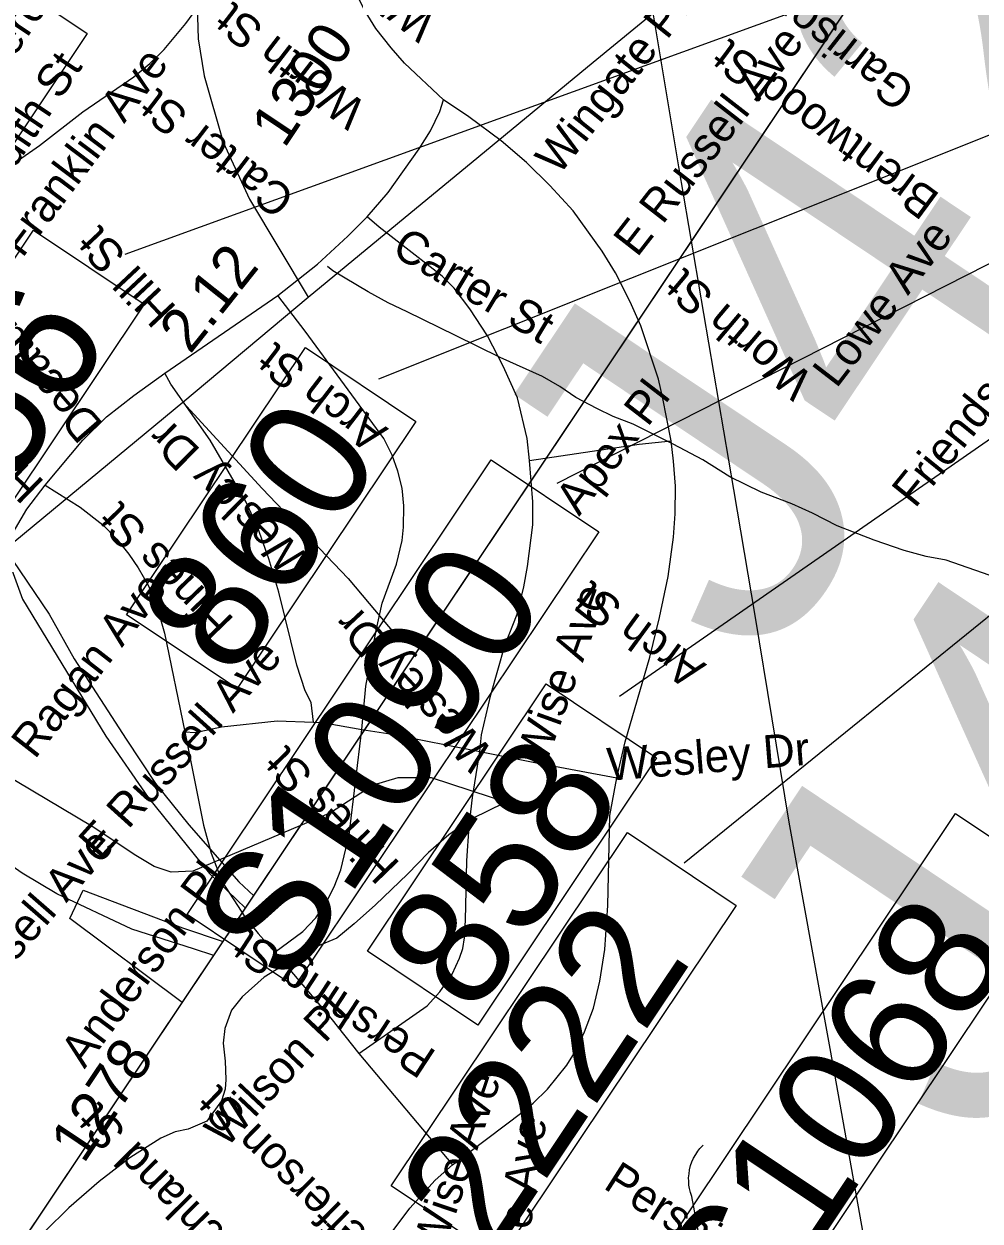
# Model space of a CAD drawing. Extents: x 1716282 to 1717158, y 799307 to 801078.
# Drawn here: x 1716855.7 to 1716895.7, y 800733.7 to 800783.8 of the extents above; entities that cross this region are included whole.
import ezdxf

# ---------------------------------------------------------------- set-up
doc = ezdxf.new("R2010")
doc.units = 0
for name, color, linetype in [('Exist Boundary Political City Limit New', 7, 'Continuous'), ('Exist Hydrographic Misc Water Feature', 7, 'Continuous'), ('Exist Road Non-System Structure Non-Sys Other Number Label', 7, 'Continuous'), ('Exist Road Non-System Type 51', 7, 'Continuous'), ('Exist Road Non-System Type 51 Label', 7, 'Continuous'), ('Exist Road Primary Interstate Structure Ovrhead Sign CELL', 7, 'Continuous'), ('Exist Road Primary NC Attributed', 7, 'Continuous'), ('Exist Road Primary US Structure Ovrhead Sign CELL', 7, 'Continuous'), ('Exist Road Primary US Structure Pipe Number Label', 7, 'Continuous'), ('Exist Road Primary US Structure Standard Bridge Number Label', 7, 'Continuous'), ('Exist Road Secondary Mileage Tenths English Label', 7, 'Continuous'), ('Exist Road Secondary Type 51 Attributed', 7, 'Continuous'), ('Exist Road Secondary Type 51 Number Label', 7, 'Continuous'), ('Exist Utilities Electrical Transmission Line', 7, 'Continuous'), ('Map Preparation Boundary City Limit Buffer Line', 7, 'Continuous'), ('Prop DSN Text', 7, 'Continuous')]:
    doc.layers.add(name, color=color, linetype=linetype)

msp = doc.modelspace()

# ---------------------------------------------------------------- linework, layer by layer
at = {"layer": 'Exist Boundary Political City Limit New'}
for points in [[(1716834.11, 800763.795), (1716833.305, 800760.022), (1716832.112, 800757.372), (1716829.513, 800751.6), (1716828.118, 800748.504), (1716830.111, 800743.692), (1716849.41, 800759.889), (1716847.021, 800765.269), (1716846.178, 800767.852), (1716845.613, 800770.743), (1716845.226, 800773.688), (1716850.853, 800766.071), (1716851.697, 800766.703), (1716854.143, 800763.725), (1716855.625, 800759.697), (1716859.113, 800753.96), (1716860.899, 800751.388), (1716863.463, 800748.209), (1716864.965, 800746.757)], [(1716862.323, 800742.81), (1716857.612, 800746.321), (1716858.169, 800747.509), (1716862.329, 800745.932), (1716864.031, 800745.362)]]:
    msp.add_lwpolyline(points, dxfattribs=at)
at = {"layer": 'Exist Hydrographic Misc Water Feature'}
for points in [[(1716896.454, 800760.586), (1716894.33, 800761.333), (1716893.487, 800761.488), (1716892.565, 800761.731), (1716891.314, 800762.164), (1716889.76, 800762.769), (1716888.721, 800763.304), (1716887.855, 800763.685), (1716886.574, 800764.173), (1716885.261, 800764.824), (1716884.126, 800765.528), (1716882.895, 800766.193), (1716881.216, 800767.025), (1716880.381, 800767.347), (1716879.693, 800767.677), (1716878.814, 800768.139), (1716878.143, 800768.597), (1716877.415, 800769.023), (1716875.638, 800769.815), (1716873.775, 800770.739), (1716871.751, 800771.736), (1716870.949, 800772.106), (1716870.11, 800772.573), (1716868.631, 800773.443), (1716868.408, 800773.63)], [(1716876.042, 800751.14), (1716872.76, 800752.217), (1716871.349, 800752.22), (1716870.316, 800751.909), (1716868.528, 800750.75), (1716862.768, 800748.302), (1716861.859, 800748.263), (1716861.14, 800748.508), (1716860.381, 800748.958), (1716858.551, 800750.182), (1716851.597, 800754.307), (1716846.485, 800758.817), (1716843.528, 800759.819), (1716840.189, 800759.612), (1716836.246, 800760.699), (1716833.061, 800762.288), (1716827.152, 800765.878), (1716824.331, 800768.986), (1716822.573, 800770.041), (1716821.851, 800770.088)], [(1716875.987, 800751.251), (1716874.936, 800750.732), (1716874.44, 800750.504), (1716873.496, 800749.833), (1716872.636, 800749.086), (1716871.761, 800748.174), (1716870.421, 800746.891), (1716869.527, 800746.096), (1716868.798, 800745.505), (1716867.619, 800745.013), (1716865.746, 800743.866), (1716864.837, 800743.049), (1716864.379, 800742.482), (1716864.106, 800741.721), (1716864.034, 800741.101), (1716864.115, 800740.346), (1716864.153, 800739.58), (1716864.125, 800739.178), (1716863.967, 800738.688), (1716863.353, 800737.843), (1716862.562, 800737.507), (1716862.021, 800737.384), (1716861.423, 800737.125), (1716860.118, 800736.295), (1716858.844, 800735.303), (1716857.569, 800734.207), (1716856.583, 800733.23)]]:
    msp.add_lwpolyline(points, dxfattribs=at)
at = {"layer": 'Exist Road Non-System Type 51'}
for p, q in [((1716861.586, 800769.158), (1716866.326, 800772.415)), ((1716869.721, 800740.677), (1716873.65, 800736.011))]:
    msp.add_line(p, q, dxfattribs=at)
for points in [[(1716873.268, 800780.604), (1716871.626, 800782.148), (1716871.068, 800782.779), (1716870.435, 800783.591), (1716869.985, 800784.322), (1716869.676, 800784.941), (1716869.32, 800785.79), (1716869.061, 800786.567), (1716868.648, 800788.468), (1716868.622, 800789.284)], [(1716842.177, 800775.411), (1716842.533, 800775.21), (1716842.752, 800775.21), (1716843.723, 800775.6), (1716844.159, 800775.703), (1716844.543, 800775.743), (1716848.824, 800775.818), (1716850.05, 800775.959), (1716851.719, 800776.353), (1716853.383, 800776.943), (1716854.509, 800777.498), (1716855.466, 800778.077), (1716856.334, 800778.695), (1716858.161, 800780.1), (1716860.29, 800781.57), (1716860.959, 800782.125), (1716861.565, 800782.714), (1716862.464, 800783.805), (1716863.245, 800784.863)], [(1716870.072, 800775.714), (1716870.95, 800776.725), (1716872.253, 800778.555), (1716872.716, 800779.303), (1716873.119, 800780.115), (1716873.268, 800780.604)], [(1716882.799, 800766.321), (1716882.446, 800768.175), (1716882.272, 800768.914), (1716881.539, 800771.149), (1716881.094, 800772.147), (1716880.467, 800773.36), (1716879.918, 800774.271), (1716878.706, 800775.956), (1716877.727, 800777.024), (1716876.75, 800777.986), (1716875.68, 800778.885), (1716874.323, 800779.889), (1716873.268, 800780.604)], [(1716866.326, 800772.415), (1716867.991, 800773.732), (1716869.254, 800774.902), (1716870.072, 800775.714)], [(1716876.867, 800765.497), (1716876.773, 800766.419), (1716876.374, 800768.126), (1716875.772, 800769.458), (1716875.105, 800770.725), (1716874.372, 800771.861), (1716873.711, 800772.715), (1716873.209, 800773.23), (1716870.569, 800775.281), (1716870.072, 800775.714)], [(1716869.842, 800754.234), (1716870.013, 800756.052), (1716870.443, 800758.384), (1716870.698, 800759.528), (1716871.299, 800761.159), (1716871.531, 800762.157), (1716871.591, 800762.712), (1716871.598, 800763.611), (1716871.535, 800764.344), (1716871.358, 800765.054), (1716871.118, 800765.727), (1716870.764, 800766.43), (1716867.471, 800770.925), (1716866.326, 800772.415)], [(1716856.579, 800764.477), (1716858.153, 800766.35), (1716859.145, 800767.331), (1716860.288, 800768.232), (1716861.586, 800769.158)], [(1716867.823, 800754.552), (1716867.728, 800755.365), (1716867.464, 800755.854), (1716867.125, 800756.927), (1716866.371, 800759.984), (1716865.949, 800761.391), (1716865.482, 800762.684), (1716864.993, 800763.759), (1716863.49, 800766.359), (1716861.84, 800768.698), (1716861.586, 800769.158)], [(1716876.867, 800765.497), (1716881.471, 800766.184), (1716882.799, 800766.321)], [(1716880.523, 800752.219), (1716880.881, 800753.725), (1716881.905, 800757.266), (1716882.314, 800758.925), (1716882.678, 800760.646), (1716882.904, 800762.29), (1716882.973, 800763.269), (1716882.981, 800764.428), (1716882.906, 800765.482), (1716882.799, 800766.321)], [(1716874.782, 800753.323), (1716874.852, 800754.022), (1716875.246, 800755.686), (1716875.834, 800757.761), (1716876.347, 800759.062), (1716876.629, 800760.215), (1716876.786, 800761.058), (1716877.009, 800762.815), (1716877.006, 800763.769), (1716876.867, 800765.497)], [(1716852.694, 800753.43), (1716853.477, 800757.962), (1716854.094, 800759.998), (1716854.689, 800761.46), (1716855.096, 800762.246), (1716855.813, 800763.469), (1716856.579, 800764.477)], [(1716856.579, 800764.477), (1716858.043, 800763.551), (1716858.998, 800762.803), (1716859.58, 800762.206), (1716860.086, 800761.588), (1716860.48, 800761.015), (1716860.886, 800760.279), (1716861.227, 800759.488), (1716861.577, 800758.274), (1716862.428, 800754.145)], [(1716862.428, 800754.145), (1716862.859, 800754.119), (1716863.966, 800754.357), (1716866.292, 800754.604), (1716867.823, 800754.552)], [(1716867.823, 800754.552), (1716868.2, 800754.533), (1716869.842, 800754.234)], [(1716862.428, 800754.145), (1716863.211, 800750.232), (1716863.536, 800749.063), (1716863.987, 800747.863), (1716864.942, 800746.399), (1716865.499, 800745.693), (1716866.196, 800744.915)], [(1716866.196, 800744.915), (1716867.376, 800745.774), (1716867.921, 800746.357), (1716868.361, 800747.02), (1716868.685, 800747.65), (1716868.961, 800748.368), (1716869.318, 800749.826), (1716869.842, 800754.234)], [(1716869.842, 800754.234), (1716871.119, 800754.049), (1716874.782, 800753.323)], [(1716869.721, 800740.677), (1716872.583, 800742.668), (1716873.116, 800743.247), (1716873.626, 800743.994), (1716873.936, 800744.663), (1716874.076, 800745.062), (1716874.145, 800745.516), (1716874.195, 800746.248), (1716874.247, 800748.74), (1716874.344, 800750.192), (1716874.479, 800751.392), (1716874.782, 800753.323)], [(1716874.782, 800753.323), (1716877.095, 800752.852), (1716880.523, 800752.219)], [(1716873.65, 800736.011), (1716876.55, 800738.196), (1716877.025, 800738.591), (1716877.627, 800739.182), (1716878.438, 800740.188), (1716878.826, 800740.803), (1716879.181, 800741.578), (1716879.552, 800742.566), (1716879.823, 800743.702), (1716880.02, 800745.022), (1716880.155, 800746.865), (1716880.239, 800750.632), (1716880.523, 800752.219)], [(1716866.196, 800744.915), (1716868.545, 800742.143), (1716869.721, 800740.677)], [(1716884.089, 800732.43), (1716883.672, 800734.687), (1716883.615, 800734.854), (1716883.576, 800735.022), (1716883.549, 800735.154), (1716883.541, 800735.325), (1716883.538, 800735.464), (1716883.555, 800735.627), (1716883.578, 800735.804), (1716883.621, 800735.973), (1716883.674, 800736.134), (1716883.745, 800736.287), (1716883.833, 800736.44), (1716883.929, 800736.577), (1716884.008, 800736.687), (1716884.143, 800736.828)], [(1716869.135, 800715.833), (1716868.519, 800718.609), (1716868.059, 800720.993), (1716867.85, 800723.144), (1716867.829, 800723.874), (1716867.884, 800724.886), (1716868.041, 800726.256), (1716868.341, 800727.592), (1716868.632, 800728.704), (1716868.938, 800729.409), (1716869.514, 800730.6), (1716870.141, 800731.727), (1716871.115, 800733.201), (1716871.849, 800734.189), (1716872.919, 800735.364), (1716873.65, 800736.011)]]:
    msp.add_lwpolyline(points, dxfattribs=at)
at = {"layer": 'Exist Road Primary Interstate Structure Ovrhead Sign CELL'}
msp.add_lwpolyline([(1716881.982, 800731.684), (1716894.725, 800750.723), (1716899.233, 800747.705), (1716886.49, 800728.666)], close=True, dxfattribs=at)
at = {"layer": 'Exist Road Primary NC Attributed'}
for p, q in [((1716862.35, 800767.942), (1716867.599, 800772.349)), ((1716854.901, 800761.795), (1716862.35, 800767.942))]:
    msp.add_line(p, q, dxfattribs=at)
msp.add_lwpolyline([(1716867.599, 800772.349), (1716871.334, 800775.429), (1716874.74, 800778.239), (1716879.543, 800782.182), (1716888.216, 800789.306), (1716895.583, 800795.371), (1716897.845, 800797.368), (1716900.138, 800799.371), (1716900.27, 800799.505)], dxfattribs=at)
at = {"layer": 'Exist Road Primary US Structure Ovrhead Sign CELL'}
msp.add_line((1716918.534, 800785.134), (1716878.021, 800764.547), dxfattribs=at)
for points in [[(1716841.091, 800767.359), (1716853.834, 800786.398), (1716858.342, 800783.38), (1716845.599, 800764.341)], [(1716862.521, 800746.495), (1716875.264, 800765.534), (1716879.773, 800762.517), (1716867.03, 800743.478)]]:
    msp.add_lwpolyline(points, close=True, dxfattribs=at)
at = {"layer": 'Exist Road Primary US Structure Standard Bridge Number Label'}
for p, q in [((1716921.942, 800789.433), (1716870.539, 800768.914)), ((1716928.65, 800788.963), (1716880.646, 800755.621)), ((1716898.368, 800788.083), (1716859.92, 800774.132)), ((1716928.805, 800785.481), (1716883.35, 800748.637))]:
    msp.add_line(p, q, dxfattribs=at)
for points in [[(1716848.6, 800763.956), (1716856.093, 800775.15), (1716860.721, 800772.052), (1716853.229, 800760.858)], [(1716859.988, 800759.047), (1716867.481, 800770.241), (1716872.109, 800767.143), (1716864.617, 800755.949)], [(1716870.077, 800744.959), (1716877.57, 800756.153), (1716882.198, 800753.055), (1716874.706, 800741.861)], [(1716871.075, 800735.132), (1716880.977, 800749.925), (1716885.533, 800746.875), (1716875.632, 800732.082)]]:
    msp.add_lwpolyline(points, close=True, dxfattribs=at)
at = {"layer": 'Exist Road Secondary Type 51 Attributed'}
for points in [[(1716862.884, 800789.028), (1716862.882, 800786.871), (1716862.99, 800783.159), (1716863.243, 800781.618), (1716864.034, 800778.831), (1716865.143, 800776.452), (1716867.599, 800772.349)], [(1716862.35, 800767.942), (1716865.674, 800764.329), (1716869.275, 800760.558), (1716871.25, 800758.2)], [(1716854.901, 800761.795), (1716856.738, 800759.069), (1716857.795, 800757.192), (1716859.968, 800753.831), (1716861.201, 800751.972), (1716862.593, 800750.251), (1716864.697, 800747.863), (1716865.314, 800747.278)], [(1716863.638, 800744.774), (1716862.791, 800745.056), (1716860.214, 800745.883), (1716857.066, 800747.35), (1716855.617, 800748.225), (1716852.954, 800750.061)]]:
    msp.add_lwpolyline(points, dxfattribs=at)
at = {"layer": 'Exist Utilities Electrical Transmission Line'}
msp.add_lwpolyline([(1716891.042, 800732.059), (1716889.678, 800739.724), (1716887.751, 800750.356), (1716886.331, 800759.011), (1716885.425, 800764.285), (1716883.133, 800777.808), (1716880.36, 800794.405), (1716879.81, 800798.907), (1716878.572, 800805.747), (1716876.827, 800815.618), (1716875.736, 800821.896), (1716874.127, 800831.603), (1716872.289, 800842.52), (1716871.049, 800850.314), (1716869.866, 800856.867), (1716868.611, 800863.725)], dxfattribs=at)
at = {"layer": 'Map Preparation Boundary City Limit Buffer Line'}
for points in [[(1716834.11, 800763.795), (1716833.305, 800760.022), (1716832.112, 800757.372), (1716829.513, 800751.6), (1716828.118, 800748.504), (1716830.111, 800743.692), (1716849.41, 800759.889), (1716847.021, 800765.269), (1716846.178, 800767.852), (1716845.613, 800770.743), (1716845.226, 800773.688), (1716850.853, 800766.071), (1716851.697, 800766.703), (1716854.143, 800763.725), (1716855.625, 800759.697), (1716859.113, 800753.96), (1716860.899, 800751.388), (1716863.463, 800748.209), (1716864.965, 800746.757)], [(1716862.323, 800742.81), (1716857.612, 800746.321), (1716858.169, 800747.509), (1716862.329, 800745.932), (1716864.031, 800745.362)]]:
    msp.add_lwpolyline(points, dxfattribs=at)
at = {"layer": 'Prop DSN Text'}
for points in [[(1716644.267, 800417.02), (1716922.463, 800832.664), (1716560.178, 801075.146), (1716281.982, 800659.503)], [(1716644.267, 800417.02), (1716922.463, 800832.664), (1716967.08, 800802.801), (1716688.884, 800387.158)]]:
    msp.add_lwpolyline(points, close=True, dxfattribs=at)

# ---------------------------------------------------------------- texts
at = {"layer": 'Exist Road Non-System Structure Non-Sys Other Number Label'}
for s, p in [('J422', (1716886.6, 800756.411)), ('J425', (1716896.122, 800736.208))]:
    msp.add_text(s, height=15.223, rotation=56.2051, dxfattribs=at).set_placement(p)
at = {"layer": 'Exist Road Non-System Type 51 Label'}
for s, rotation, p in [('Winslow St', 141.7726, (1716873.087, 800784.034)), ('E Commerce Ave', 56.2051, (1716851.269, 800776.381)), ('Garrison St', 141.9054, (1716893.121, 800781.129)), ('Wingate Pl', 51.4506, (1716878.094, 800777.404)), ('Worth St', 142.4718, (1716870.108, 800780.38)), ('E Russell Ave', 52.0765, (1716881.378, 800773.978)), ('Brentwood St', 143.5228, (1716894.119, 800776.624)), ('Meredith St', 56.2051, (1716852.931, 800774.185)), ('Franklin Ave', 52.9242, (1716855.625, 800773.953)), ('Carter St', 142.618, (1716867.12, 800776.656)), ('Hill St', 133.1778, (1716862.127, 800771.901)), ('Lowe Ave', 52.4582, (1716889.729, 800768.49)), ('Carter St', 329.01, (1716871.035, 800774.161)), ('Decatur St', 130.9654, (1716859.057, 800767.015)), ('Worth St', 139.8685, (1716888.813, 800768.992)), ('Friends Ave', 51.0378, (1716893.022, 800763.466)), ('Arch St', 142.5163, (1716870.991, 800766.825)), ('Hines St', 135.811, (1716856.593, 800764.591)), ('Apex Pl', 52.445, (1716878.948, 800763.141)), ('Wesley Dr', 135.4437, (1716867.803, 800761.339)), ('Hines St', 133.9789, (1716864.543, 800758.84)), ('Ragan Ave', 52.1122, (1716856.142, 800752.958)), ('Arch St', 143.8373, (1716884.317, 800756.952)), ('Wise Ave', 70.1644, (1716877.538, 800752.687)), ('Wesley Dr', 133.1033, (1716875.419, 800753.294)), ('E Russell Ave', 47.9277, (1716858.885, 800748.735)), ('Wesley Dr', 4.5891, (1716880.177, 800752.088)), ('Hines St', 133.9789, (1716871.495, 800748.614)), ('E Russell Ave', 48.9259, (1716852.009, 800740.703)), ('Anderson Pl', 53.2347, (1716858.224, 800739.998)), ('Pershing St', 146.8343, (1716873.03, 800740.72)), ('Wilson Pl', 46.7374, (1716864.15, 800736.672)), ('Wise Ave', 71.4686, (1716873.211, 800732.22)), ('Jefferson St', 135.5518, (1716870.834, 800732.534)), ('Richland St', 134.6514, (1716865.43, 800731.977)), ('Lake Ave', 81.5617, (1716876.468, 800730.326)), ('Pershing St', 327.4147, (1716879.916, 800735.053))]:
    msp.add_text(s, height=1.3775, rotation=rotation, dxfattribs=at).set_placement(p)
at = {"layer": 'Exist Road Primary Interstate Structure Ovrhead Sign CELL'}
msp.add_text('S1068', height=5.075, rotation=56.2051, dxfattribs=at).set_placement((1716886.221, 800728.566))
at = {"layer": 'Exist Road Primary US Structure Ovrhead Sign CELL'}
msp.add_text('S1090', height=5.075, rotation=56.2051, dxfattribs=at).set_placement((1716866.76, 800743.377))
at = {"layer": 'Exist Road Primary US Structure Pipe Number Label'}
msp.add_text('P575', height=5.075, rotation=56.2051, dxfattribs=at).set_placement((1716897.78, 800725.234))
at = {"layer": 'Exist Road Primary US Structure Standard Bridge Number Label'}
for s, p in [('856', (1716853.092, 800761.169)), ('860', (1716864.48, 800756.26)), ('858', (1716874.569, 800742.171)), ('2222', (1716875.315, 800732.04))]:
    msp.add_text(s, height=5.075, rotation=56.2051, dxfattribs=at).set_placement(p)
at = {"layer": 'Exist Road Secondary Mileage Tenths English Label'}
msp.add_text('2.12', height=1.8125, rotation=51.4365, dxfattribs=at).set_placement((1716862.647, 800769.924))
at = {"layer": 'Exist Road Secondary Type 51 Number Label'}
for s, p in [('1300', (1716866.598, 800778.538)), ('1278', (1716858.189, 800736.014))]:
    msp.add_text(s, height=1.8125, rotation=56.2051, dxfattribs=at).set_placement(p)

doc.saveas('drawing.dxf')
